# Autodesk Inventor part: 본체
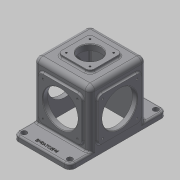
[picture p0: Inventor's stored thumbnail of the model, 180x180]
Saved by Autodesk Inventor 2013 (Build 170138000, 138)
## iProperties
Created: 2018-09
Part Number: 본체
Material: 일반
Document SubType Name: Modeling
Designer: mduedu
Density: 1 g/cm^3
Author: mduedu
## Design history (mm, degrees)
sketch "스케치1"
  geometry: L1 (90, 52.5)-(-90, 52.5); L2 (-90, 52.5)-(-90, -52.5); L3 (-90, -52.5)-(90, -52.5); L4 (90, -52.5)-(90, 52.5); L5 (90, 52.5)-(-90, -52.5); L6 (-90, 52.5)-(90, -52.5); 1 further point
  constraints: 12 end point, 2 midpoint, 2 parallel, 1 horizontal, 1 perpendicular
  dimensions: "d0" = 180 distance of L3.end L2.end; "d1" = 105 distance of L2.end L1.end
extrude "돌출1" new body sketch "스케치1" distance "d2" = 10; taper "d3" = 0 deg
sketch "스케치2"
  geometry: L1 (-52.5, -52.5)-(52.5, -52.5); L2 (52.5, -52.5)-(52.5, 52.5); L3 (52.5, 52.5)-(-52.5, 52.5); L4 (-52.5, 52.5)-(-52.5, -52.5); L5 (-52.5, -52.5)-(52.5, 52.5); L6 (52.5, -52.5)-(-52.5, 52.5); 1 further point
  constraints: 12 end point, 2 midpoint, 2 parallel, 1 horizontal, 1 perpendicular
  dimensions: "d4" = 105 distance of L3.end L2.end; "d5" = 105 distance of L2.end L1.end
extrude "돌출2" join sketch "스케치2" distance "d6" = 105; taper "d7" = 0 deg
node "작업 평면1"
sketch "스케치3"
  geometry: L1 (-52.5, 52.5)-(52.5, 52.5) reference; L2 (52.5, 52.5)-(52.5, -52.5) reference; L3 (52.5, -52.5)-(-52.5, -52.5) reference; L4 (-52.5, -52.5)-(-52.5, 52.5) reference; L5 (46.5, 46.5)-(-46.5, 46.5); L6 (-46.5, 46.5)-(-46.5, -46.5); L7 (-46.5, -46.5)-(46.5, -46.5); L8 (46.5, -46.5)-(46.5, 46.5); 1 further point
  constraints: 8 end point, 3 other
  dimensions: "d9" = 6 distance between parallel lines of L5 L1
extrude "돌출3" cut sketch "스케치3" stored distance "d10" = 105; taper "d11" = 0 deg
fillet "모깎기1" dims "d12" = 9
fillet "모깎기2" dims "d13" = 9
fillet "모깎기3" dims "d14" = 3
fillet "모깎기4" dims "d15" = 3
sketch "스케치4"
  geometry: L1 (-30, -30)-(30, -30); L2 (30, -30)-(30, 30); L3 (30, 30)-(-30, 30); L4 (-30, 30)-(-30, -30); L5 (-30, -30)-(30, 30); L6 (30, -30)-(-30, 30); 1 further point
  constraints: 12 end point, 2 midpoint, 2 parallel, 1 horizontal, 1 perpendicular
  dimensions: "d16" = 60 distance of L3.end L2.end; "d17" = 60 distance of L2.end L1.end
extrude "돌출4" join sketch "스케치4" distance "d18" = 5; taper "d19" = 0 deg
fillet "모깎기5" dims "d20" = 8
fillet "모깎기6" dims "d21" = 3
sketch "스케치5"
  geometry: C1 r 20 at (0, 0); 1 further point
  constraints: 1 centre point, 1 coincident
  dimensions: "d22" = 40 diameter of C1
extrude "돌출5" cut sketch "스케치5" stored distance "d23" = 5; taper "d24" = 0 deg
sketch "스케치6"
  geometry: L1 (50, 17.5)-(130, 17.5); L2 (130, 17.5)-(130, 97.5); L3 (130, 97.5)-(50, 97.5); L4 (50, 97.5)-(50, 17.5); L5 (50, 17.5)-(130, 97.5); L6 (130, 17.5)-(50, 97.5); L7 (0, 0)-(180, 0) reference; 4 further points
  constraints: 12 end point, 4 midpoint, 2 parallel, 1 horizontal, 1 perpendicular, 1 vertical alignment
  dimensions: "d25" = 80 distance of L3.end L2.end; "d26" = 80 distance of L2.end L1.end; "d27" = 57.5 distance of point (90, 0) point (90, 57.5)
extrude "돌출6" join sketch "스케치6" distance "d28" = 3; taper "d29" = 0 deg
fillet "모깎기7" dims "d30" = 8
sketch "스케치7"
  geometry: C1 r 32.5 at (90, 57.5); 1 further point
  constraints: 1 centre point, 1 vertical alignment
  dimensions: "d32" = 65 diameter of C1; "d33" = 57.5 distance of C1.centre point (90, 0)
extrude "돌출7" cut sketch "스케치7" stored distance "d34" = 3; taper "d35" = 0 deg
fillet "모깎기9" dims "d36" = 3
sketch "스케치8"
  geometry: L1 (3.5, 7.5)-(83.5, 7.5); L2 (83.5, 7.5)-(83.5, 87.5); L3 (83.5, 87.5)-(3.5, 87.5); L4 (3.5, 87.5)-(3.5, 7.5); L5 (3.5, 7.5)-(83.5, 87.5); L6 (83.5, 7.5)-(3.5, 87.5); L7 (-9, -10)-(96, -10) reference; C1 r 32.5 at (43.5, 47.5); 4 further points
  constraints: 12 end point, 4 midpoint, 2 parallel, 1 centre point, 1 coincident, 1 horizontal, 1 perpendicular, 1 vertical alignment
  dimensions: "d37" = 80 distance of L3.end L2.end; "d38" = 80 distance of L2.end L1.end; "d39" = 57.5 distance from line of point (43.5, 47.5) L7; "d40" = 65 diameter of C1
extrude "돌출8" join sketch "스케치8" distance "d41" = 3; taper "d42" = 0 deg
fillet "모깎기10" dims "d43" = 8
extrude "돌출9" cut sketch "스케치8" stored distance "d44" = 3; taper "d45" = 0 deg
fillet "모깎기11" dims "d46" = 3
sketch "스케치9"
  geometry: L1 (50, 89.5)-(50, 25.5) reference; L2 (58, 17.5)-(122, 17.5) reference; L3 (130, 25.5)-(130, 89.5) reference; L4 (122, 97.5)-(58, 97.5) reference; C1 r 32.5 at (90, 57.5) reference; A1 r 8 centre (58, 89.5) between (58, 97.5) and (50, 89.5) reference; A2 r 8 centre (58, 25.5) between (50, 25.5) and (58, 17.5) reference; A3 r 8 centre (122, 25.5) between (122, 17.5) and (130, 25.5) reference; A4 r 8 centre (122, 89.5) between (130, 89.5) and (122, 97.5) reference; 5 further points
  constraints: 4 coincident
hole "구멍1" sketch "스케치9" at (58, 89.5), (122, 89.5), (122, 25.5), (58, 25.5) diameter "d47" = 3.242; stored, may be unused: countersink angle "d51" = 90 deg, drill point angle "d53" = 118 deg; dims "d48" = 6, "d49" = 4, "d50" = 2, "d52" = 9
sketch "스케치10"
  geometry: L1 (11.5, 7.5)-(75.5, 7.5) reference; L2 (83.5, 15.5)-(83.5, 79.5) reference; L3 (75.5, 87.5)-(11.5, 87.5) reference; L4 (3.5, 79.5)-(3.5, 15.5) reference; C1 r 32.5 at (43.5, 47.5) reference; A1 r 8 centre (11.5, 15.5) between (3.5, 15.5) and (11.5, 7.5) reference; A2 r 8 centre (75.5, 15.5) between (75.5, 7.5) and (83.5, 15.5) reference; A3 r 8 centre (75.5, 79.5) between (83.5, 79.5) and (75.5, 87.5) reference; A4 r 8 centre (11.5, 79.5) between (11.5, 87.5) and (3.5, 79.5) reference; 5 further points
  constraints: 4 coincident
hole "구멍2" sketch "스케치10" at (11.5, 79.5), (75.5, 79.5), (75.5, 15.5), (11.5, 15.5) diameter "d54" = 3.242; stored, may be unused: countersink angle "d58" = 90 deg, drill point angle "d60" = 118 deg; dims "d55" = 6, "d56" = 4, "d57" = 2, "d59" = 9
sketch "스케치11"
  geometry: L1 (22, 30)-(-22, 30) reference; L2 (-30, 22)-(-30, -22) reference; L3 (-22, -30)-(22, -30) reference; L4 (30, -22)-(30, 22) reference; C1 r 20 at (0, 0) reference; A1 r 8 centre (22, 22) between (30, 22) and (22, 30) reference; A2 r 8 centre (-22, 22) between (-22, 30) and (-30, 22) reference; A3 r 8 centre (-22, -22) between (-30, -22) and (-22, -30) reference; A4 r 8 centre (22, -22) between (22, -30) and (30, -22) reference; 5 further points
  constraints: 4 coincident
hole "구멍3" sketch "스케치11" at (-22, 22), (22, 22), (22, -22), (-22, -22) diameter "d61" = 3.242; stored, may be unused: countersink angle "d65" = 90 deg, drill point angle "d67" = 118 deg; dims "d62" = 7, "d63" = 4, "d64" = 2, "d66" = 9
fillet "모깎기12" dims "d68" = 10
sketch "스케치12"
  geometry: L1 (-90, 42.5)-(-90, -42.5) reference; L2 (-80, -52.5)-(-43.5, -52.5) reference; L3 (-52.5, -43.5)-(-52.5, 43.5) reference; L4 (-43.5, 52.5)-(-80, 52.5) reference; A1 r 10 centre (-80, 42.5) between (-80, 52.5) and (-90, 42.5) reference; A2 r 10 centre (-80, -42.5) between (-90, -42.5) and (-80, -52.5) reference; A3 r 9 centre (-43.5, -43.5) between (-52.5, -43.5) and (-43.5, -52.5) reference; A4 r 9 centre (-43.5, 43.5) between (-43.5, 52.5) and (-52.5, 43.5) reference; 3 further points
  constraints: 2 coincident
hole "구멍4" sketch "스케치12" at (-80, 42.5), (-80, -42.5) diameter "d70" = 10; stored, may be unused: countersink angle "d74" = 90 deg, drill point angle "d76" = 118 deg; dims "d71" = 6, "d72" = 4, "d73" = 2, "d75" = 9
fillet "모깎기13" dims "d77" = 3
fillet "모깎기14" dims "d78" = 3
chamfer "모따기1" distance "d79" = 1; stored, may be unused: second distance "d80" = 2, angle "d81" = 45 deg
sketch "스케치13"
  geometry: L1 (90, -42.5)-(90, 42.5) reference; 2 further points
  constraints: 1 horizontal alignment, 1 other
  dimensions: "d82" = 10 distance from line of point (80, 0) L1
feature "엠보싱1" sketch "스케치13" dims "d83" = 0.5, "d84" = 0
node "솔리드1"
mirror "대칭1"
mirror "대칭2"
mirror "대칭3"
node "투영된 루프1"
node "투영된 루프2"
node "투영된 루프3"
node "투영된 루프4"
node "투영된 루프5"
other parameters: "d8" = -6
